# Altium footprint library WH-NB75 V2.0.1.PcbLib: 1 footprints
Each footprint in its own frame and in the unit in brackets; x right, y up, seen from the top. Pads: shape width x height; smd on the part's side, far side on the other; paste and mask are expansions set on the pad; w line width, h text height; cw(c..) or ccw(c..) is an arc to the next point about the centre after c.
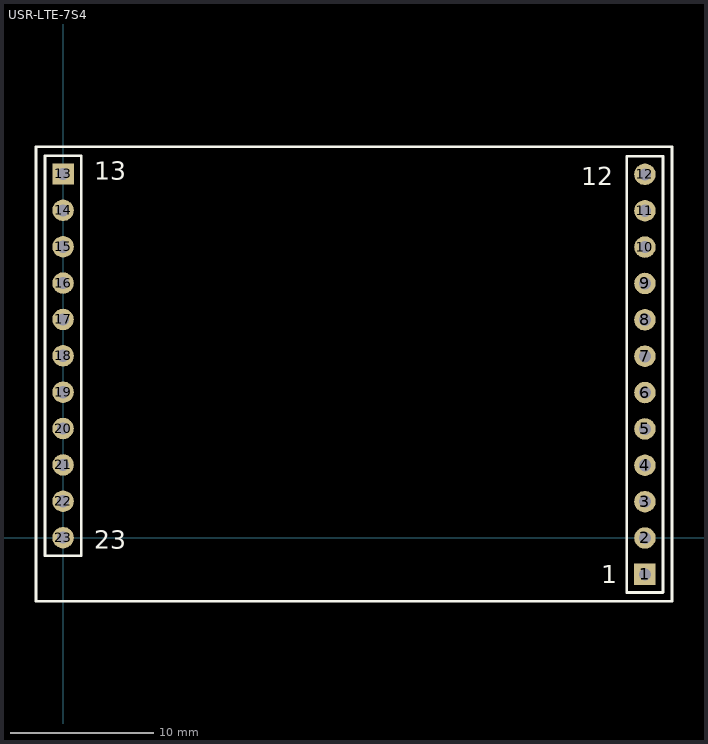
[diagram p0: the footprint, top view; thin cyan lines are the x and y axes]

## USR-LTE-7S4 [mm]
pads (23):
  rect 1.5x1.5 hole 0.85: 1(40.64,-2.565) 13(0,25.4)
  round 1.5 hole 0.85: 2(40.64,-0.025) 3(40.64,2.515) 4(40.64,5.055) 5(40.64,7.595) 6(40.64,10.135) 7(40.64,12.675) 8(40.64,15.215) 9(40.64,17.755) 10(40.64,20.295) 11(40.64,22.835) 12(40.64,25.375) 14(0,22.86) 15(0,20.32) 16(0,17.78) 17(0,15.24) 18(0,12.7) 19(0,10.16) 20(0,7.62) 21(0,5.08) 22(0,2.54) 23(0,0)
Top Overlay:
  lines w0.2: -1.27,-1.27 -1.27,24.765 -1.27,26.67 1.27,26.67 1.27,-1.27 -1.27,-1.27 ; 39.37,-3.835 41.91,-3.835 41.91,-1.93 41.91,26.645 39.37,26.645 39.37,-3.835
  lines w0.203: -1.905,-4.445 42.545,-4.445 42.545,27.305 -1.905,27.305 -1.905,-4.445
  text "23" at 2.159,-0.787 h1.27
  text "13" at 2.16,24.994 h1.27
  text "12" at 36.195,24.613 h1.27
  text "1" at 37.592,-3.2 h1.27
